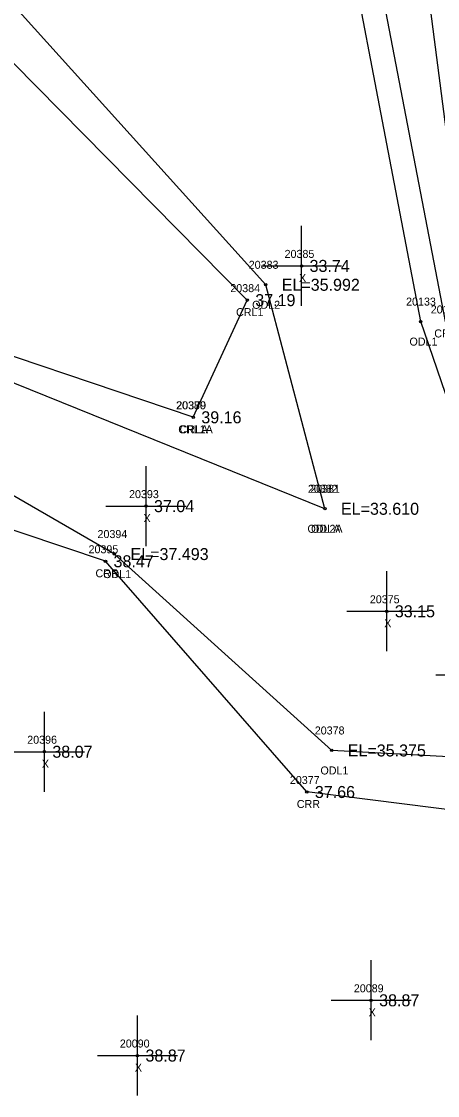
# Model space of a CAD drawing. Extents: x 2619569 to 2620117, y 784503 to 785150.
# Drawn here: x 2619752.4 to 2619804.3, y 784765.4 to 784899.6 of the extents above; entities that cross this region are included whole.
import ezdxf

# ---------------------------------------------------------------- set-up
doc = ezdxf.new("R2010")
doc.units = 0
for name, color, linetype in [('RD_DTM_BkLn2', 7, 'Continuous'), ('RD_EX_H2O', 7, 'Continuous'), ('RD_EX_H2O_txCode', 7, 'Continuous'), ('RD_EX_Misc', 7, 'Continuous'), ('RD_EX_Misc_txCode', 7, 'Continuous'), ('RD_EX_TX_H2O_ELEV', 7, 'Continuous'), ('RD_EX_TX_Misc_ELEV', 7, 'Continuous'), ('RD_SMD_Locator', 7, 'Continuous')]:
    doc.layers.add(name, color=color, linetype=linetype)

msp = doc.modelspace()

# ---------------------------------------------------------------- linework, layer by layer
at = {"layer": 'RD_DTM_BkLn2'}
msp.add_lwpolyline([(2619819.74, 784845.33), (2619814.01, 784845.92), (2619808.4, 784862.96), (2619799.16, 784934.37), (2619781.54, 785030.11), (2619769.89, 785089.15), (2619763.91, 785131.01)], dxfattribs=at)
at = {"layer": 'RD_EX_H2O'}
for points in [[(2619818.98, 784834.06), (2619808.97, 784842.56), (2619802.24, 784862.11), (2619788.78, 784932.49), (2619768.72, 785027.95), (2619758.97, 785087.81)], [(2619819.63, 784843.41), (2619811.5, 784844.43), (2619805.32, 784862.13), (2619791.73, 784933.03)], [(2619790.27, 784838.72), (2619782.87, 784866.71), (2619738.56, 784915.87), (2619703.69, 784928.29), (2619672.34, 784926.76), (2619648.41, 784918.34), (2619619.29, 784887.62)], [(2619773.83, 784850.15), (2619780.57, 784864.79), (2619733.81, 784912.21), (2619700.27, 784924.63), (2619672.07, 784923.77), (2619649.36, 784903.37), (2619624.57, 784890.48)], [(2619773.83, 784850.15), (2619738.99, 784861.9), (2619696.47, 784872.3), (2619650.86, 784880.63), (2619624.57, 784890.48)], [(2619790.27, 784838.72), (2619738, 784859.85), (2619695.37, 784868.64), (2619650.13, 784878.77), (2619618.3, 784884.79), (2619619.29, 784887.62)], [(2619816.45, 784807.13), (2619791.12, 784808.52), (2619763.98, 784833.06), (2619735.51, 784849.52), (2619695.73, 784853.41), (2619649.58, 784841.57), (2619599.67, 784837.83)], [(2619816.05, 784799.8), (2619788.01, 784803.33), (2619762.86, 784832.16), (2619731.33, 784842.74), (2619695.49, 784847.41), (2619650.29, 784835.61), (2619600.27, 784824.84)]]:
    msp.add_lwpolyline(points, dxfattribs=at)
at = {"layer": 'RD_EX_Misc'}
for p, q in [((2619787.35, 784864.07), (2619787.35, 784874.07)), ((2619782.35, 784869.07), (2619792.35, 784869.07)), ((2619767.92, 784834.05), (2619767.92, 784844.05)), ((2619762.92, 784839.05), (2619772.92, 784839.05)), ((2619798, 784820.91), (2619798, 784830.91)), ((2619793, 784825.91), (2619803, 784825.91)), ((2619804.14, 784817.99), (2619814.14, 784817.99)), ((2619755.22, 784803.36), (2619755.22, 784813.36)), ((2619750.22, 784808.36), (2619760.22, 784808.36)), ((2619796.04, 784772.3), (2619796.04, 784782.3)), ((2619791.04, 784777.3), (2619801.04, 784777.3)), ((2619766.85, 784765.4), (2619766.85, 784775.4)), ((2619761.85, 784770.4), (2619771.85, 784770.4))]:
    msp.add_line(p, q, dxfattribs=at)
at = {"layer": 'RD_SMD_Locator'}
for centre in [(2619787.35, 784869.07), (2619782.87, 784866.71), (2619780.57, 784864.79), (2619802.24, 784862.11), (2619773.83, 784850.15), (2619773.83, 784850.15), (2619767.92, 784839.05), (2619790.27, 784838.72), (2619790.27, 784838.72), (2619762.86, 784832.16), (2619763.98, 784833.06), (2619798, 784825.91), (2619755.22, 784808.36), (2619791.12, 784808.52), (2619788.01, 784803.33), (2619796.04, 784777.3), (2619766.85, 784770.4)]:
    msp.add_circle(centre, 0.15, dxfattribs=at)

# ---------------------------------------------------------------- texts
at = {"layer": 'RD_EX_H2O_txCode'}
for s, p in [('20383', (2619780.75, 784868.71)), ('20384', (2619778.45, 784865.79)), ('ODL2', (2619781.18, 784863.71)), ('20133', (2619800.41, 784864.11)), ('CRL1', (2619779.17, 784862.79)), ('20132', (2619803.49, 784863.13)), ('CRL1', (2619803.93, 784860.13)), ('ODL1', (2619800.83, 784859.11)), ('20380', (2619771.67, 784851.15)), ('20379', (2619771.71, 784851.15)), ('CRL1A', (2619771.95, 784848.15)), ('CRLA', (2619772.11, 784848.15)), ('20382', (2619788.15, 784840.72)), ('20381', (2619788.43, 784840.72)), ('ODL2A', (2619788.09, 784835.72)), ('ODLA', (2619788.54, 784835.72)), ('20394', (2619761.86, 784835.06)), ('20395', (2619760.74, 784833.16)), ('CRR', (2619761.61, 784830.16)), ('ODL1', (2619762.57, 784830.06)), ('20378', (2619789, 784810.52)), ('20377', (2619785.89, 784804.33)), ('ODL1', (2619789.71, 784805.52)), ('CRR', (2619786.76, 784801.33))]:
    msp.add_text(s, height=1, dxfattribs=at).set_placement(p)
at = {"layer": 'RD_EX_Misc_txCode'}
for s, p in [('20385', (2619785.23, 784870.07)), ('X', (2619787.03, 784867.07)), ('20393', (2619765.8, 784840.05)), ('X', (2619767.61, 784837.05)), ('20375', (2619795.88, 784826.91)), ('X', (2619797.68, 784823.91)), ('20396', (2619753.08, 784809.36)), ('X', (2619754.91, 784806.36)), ('20089', (2619793.88, 784778.3)), ('X', (2619795.73, 784775.3)), ('20090', (2619764.65, 784771.4)), ('X', (2619766.53, 784768.4))]:
    msp.add_text(s, height=1, dxfattribs=at).set_placement(p)
at = {"layer": 'RD_EX_TX_H2O_ELEV'}
for s, p in [('EL=35.992', (2619784.87, 784865.96)), ('37.19', (2619781.57, 784864.04)), ('39.16', (2619774.83, 784849.4)), ('39.16', (2619774.83, 784849.4)), ('EL=33.610', (2619792.27, 784837.97)), ('EL=33.610', (2619792.27, 784837.97)), ('EL=37.493', (2619765.98, 784832.31)), ('38.47', (2619763.86, 784831.41)), ('EL=35.375', (2619793.12, 784807.77)), ('37.66', (2619789.01, 784802.58))]:
    msp.add_text(s, height=1.5, dxfattribs=at).set_placement(p)
at = {"layer": 'RD_EX_TX_Misc_ELEV'}
for s, p in [('33.74', (2619788.35, 784868.32)), ('37.04', (2619768.92, 784838.3)), ('33.15', (2619799, 784825.16)), ('38.07', (2619756.22, 784807.61)), ('38.87', (2619797.04, 784776.55)), ('38.87', (2619767.85, 784769.65))]:
    msp.add_text(s, height=1.5, dxfattribs=at).set_placement(p)

doc.saveas('drawing.dxf')
